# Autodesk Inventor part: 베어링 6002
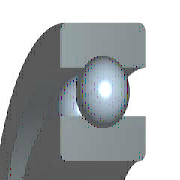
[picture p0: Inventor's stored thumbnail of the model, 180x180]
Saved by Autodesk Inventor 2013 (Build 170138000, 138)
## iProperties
Created: 2009-02
Part Number: 베어링 6002
Material: 강, 연강
Description: 깊은 그루브 볼 베어링
Document SubType Name: Modeling
Standard: KS B 2023
Designer: SeoGD™[esajin.kr]
Standards Organization: KS
Language: ko-KR
Size Designation: 6002 - 15 x 32 x 9
Categories: <MemberInstance><Categories><Category DisplayName="샤프트 부품" InternalName="7f7aeb1f-a693-4053-b835-cee3144e0d98" Mnemonic="SHFT"><Category DisplayName="베어링" Inter
Density: 1 g/cm^3
IsCustomPart: 1
Author: SeoGD™[esajin.kr]
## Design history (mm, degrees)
sketch "스케치" dims "d0" = 4.42 (= -0.26 x WD + 0.26 x BD)
  geometry: L1 (2.29, 11.75)-(6.71, 11.75); L2 (4.5, 11.75)-(4.5, 9.54); L3 (4.5, 11.75)-(4.5, 13.96); L4 (2.858, 10.271)-(0, 10.271); L5 (0, 7.5)-(9, 7.5); L6 (2.858, 13.229)-(0, 13.229); L7 (0, 16)-(9, 16); L8 (9, 7.5)-(9, 10.271); L9 (6.142, 10.271)-(9, 10.271); L10 (6.142, 13.229)-(9, 13.229); L11 (9, 16)-(9, 13.229); L12 (-1.4, 0)-(8.4, 0) reference; L13 (0, -0.3)-(0, 5.3) reference
  constraints: 22 end point, 4 point on line, 2 collinear, 2 perpendicular, 2 symmetric about line, 1 midpoint, 1 parallel, 14 other
  dimensions: "d9" = 15 diameter of L5 L12 (= WD); "d11" = 32 diameter of L7 L12 (= BD); "d12" = 9 distance between parallel lines of L8 L13 (= KB); "d13" = 20.542 diameter of L9 L12 (= 0.326 x BD + 0.674 x WD)
revolve "본체" stored, may be unused: angle "d6" = 90 deg
revolve "볼" stored, may be unused: angle "d7" = 90 deg
pattern_circular "IDS_ARRAYBALL[SIMPL:T]" dims angle "d3" = 360 deg
body "Solid1"
fillet "모깎기1" dims "d1" = 0.3 (= KRS)
other parameters: "WD" = 15 [user parameter; used in 5 equation terms], "BD" = 32 [user parameter; used in 5 equation terms], "KB" = 9 [user parameter; used in 1 equation term], "KRS" = 0.3 [user parameter; used in 1 equation term], "d4" = 0, "d5" = 0, "d8" = 0, "d14" = 0, "d15" = 0, "BBA" = 0 [user parameter], "BC0" = 2850000 [user parameter], "BC" = 5590000 [user parameter], "BR" = 16 (= 0.5 x BD) [user parameter], "WR" = 7.5 (= 0.5 x WD) [user parameter]
